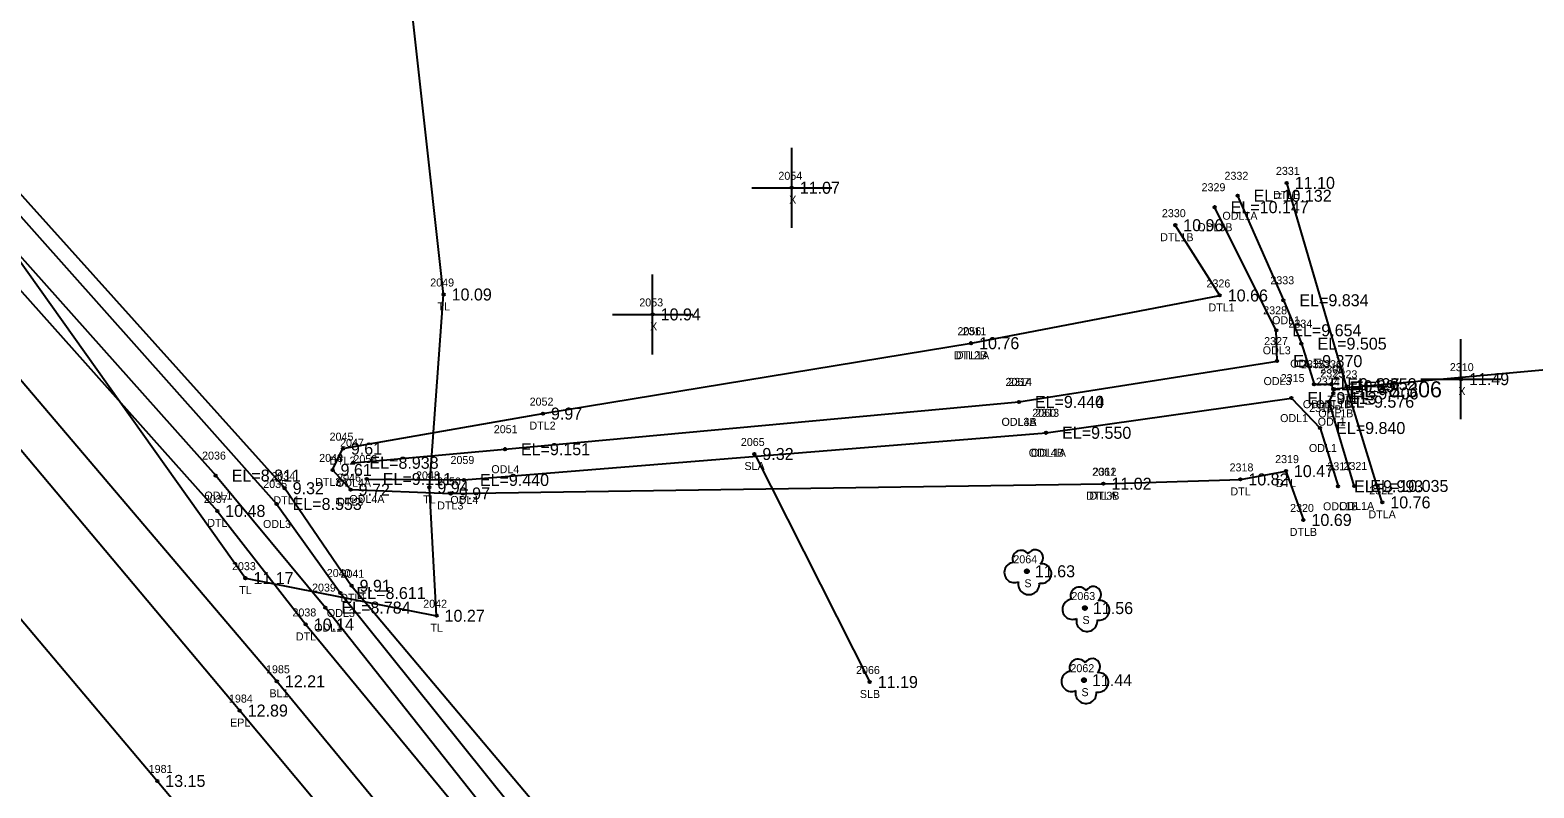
# Model space of a CAD drawing. Extents: x 2042211 to 2045853, y 303080 to 309569.
# Drawn here: x 2044179.7 to 2044367.6, y 305031.1 to 305125.9 of the extents above; entities that cross this region are included whole.
import ezdxf

# ---------------------------------------------------------------- set-up
doc = ezdxf.new("R2010")
doc.units = 0
for name, color, linetype in [('BR_500YR_SCOUR', 7, 'Continuous'), ('RD_DTM_BkLn1', 7, 'Continuous'), ('RD_DTM_BkLn_txCode', 7, 'Continuous'), ('RD_EX_DR_Pipe_txCode', 7, 'Continuous'), ('RD_EX_H2O', 7, 'Continuous'), ('RD_EX_H2O_txCode', 7, 'Continuous'), ('RD_EX_Misc', 7, 'Continuous'), ('RD_EX_Misc_txCode', 7, 'Continuous'), ('RD_EX_Road', 7, 'Continuous'), ('RD_EX_Road_txCode', 7, 'Continuous'), ('RD_EX_TX_H2O_ELEV', 7, 'Continuous'), ('RD_EX_TX_Misc_ELEV', 7, 'Continuous'), ('RD_EX_TX_Road_ELEV', 7, 'Continuous'), ('RD_EX_TX_VEG_ELEV', 7, 'Continuous'), ('RD_EX_VEG_txCode', 7, 'Continuous'), ('RD_HC_Survey_ELEV', 7, 'Continuous'), ('RD_HC_Survey_txCode', 7, 'Continuous'), ('RD_SMD_Locator', 7, 'Continuous'), ('RD_TX_Pipe_ElevEX', 7, 'Continuous')]:
    doc.layers.add(name, color=color, linetype=linetype)

msp = doc.modelspace()

# ---------------------------------------------------------------- linework, layer by layer
at = {"layer": 'BR_500YR_SCOUR'}
for p, q in [((2044376.14, 305084.11), (2044342.61, 305081.01)), ((2044270.23, 305072.92), (2044284.64, 305044.4))]:
    msp.add_line(p, q, dxfattribs=at)
msp.add_lwpolyline([(2044203.29, 305185.8), (2044187.09, 305153.29), (2044169.64, 305138.38), (2044164.21, 305129.35), (2044163.7, 305117.76), (2044206.63, 305057.39), (2044230.52, 305052.69), (2044229.62, 305068.74), (2044231.4, 305092.87), (2044226.11, 305140.65)], dxfattribs=at)
for centre, radius in [((2044231.4, 305092.87), 0.15), ((2044342.61, 305081.01), 0.2), ((2044270.23, 305072.92), 0.15), ((2044229.62, 305068.74), 0.15), ((2044304.28, 305058.25), 0.25), ((2044304.28, 305058.25), 0.15), ((2044206.63, 305057.39), 0.15), ((2044230.52, 305052.69), 0.15), ((2044311.53, 305053.65), 0.25), ((2044311.53, 305053.65), 0.15), ((2044284.64, 305044.4), 0.15), ((2044311.41, 305044.63), 0.25), ((2044311.41, 305044.63), 0.15)]:
    msp.add_circle(centre, radius, dxfattribs=at)
for centre, radius, start, end in [((2044303.56, 305059.79), 1.08, 34.9763, 204.756), ((2044305.32, 305059.95), 0.995, 308.7626, 152.0467), ((2044302.72, 305058.09), 1.26, 96.4518, 294.734), ((2044306.12, 305057.97), 1.22, 256.5667, 98.1046), ((2044304.52, 305056.65), 1.32, 166.8827, 5.7589), ((2044310.81, 305055.19), 1.08, 34.9763, 204.756), ((2044312.58, 305055.35), 0.995, 308.7626, 152.0467), ((2044309.97, 305053.49), 1.26, 96.4518, 294.734), ((2044313.37, 305053.37), 1.22, 256.5667, 98.1046), ((2044311.78, 305052.05), 1.32, 166.8827, 5.7589), ((2044310.69, 305046.18), 1.08, 34.9763, 204.756), ((2044312.46, 305046.33), 0.995, 308.7626, 152.0467), ((2044309.85, 305044.48), 1.26, 96.4518, 294.734), ((2044313.25, 305044.35), 1.22, 256.5667, 98.1046), ((2044311.66, 305043.04), 1.32, 166.8827, 5.7589)]:
    msp.add_arc(centre, radius, start, end, dxfattribs=at)
at = {"layer": 'RD_DTM_BkLn1'}
for points in [[(2043537.57, 305841.2), (2043543.07, 305834.82), (2043547.67, 305836.32), (2043557.54, 305825.5), (2043571.92, 305809.49), (2043633.83, 305732.88), (2043699.09, 305656.29), (2043762.93, 305580.55), (2043827.21, 305502.36), (2043888.69, 305425.33), (2043954.53, 305349.45), (2044014.08, 305277.47), (2044018.49, 305276.45), (2044019.61, 305275.44), (2044023.1, 305269.64), (2044024.11, 305264.85), (2044081.02, 305196.95), (2044145.48, 305121.13), (2044210.56, 305044.49), (2044273.6, 304967.95), (2044321.18, 304912.75), (2044337.82, 304895.78)], [(2043528.91, 305830.2), (2043556.35, 305797.19), (2043619.96, 305720.85), (2043684.02, 305644.21), (2043747.98, 305567.9), (2043812.35, 305491.13), (2043876, 305414.64), (2043940.22, 305337.83), (2044003.86, 305261.82), (2044067.88, 305184.94), (2044131, 305108.73), (2044195.62, 305032.03), (2044259.59, 304955.88), (2044323.63, 304879.52), (2044387.48, 304802.4), (2044451.92, 304725.21), (2044515.94, 304648.42), (2044581.15, 304571.52), (2044645.01, 304495.17), (2044708.42, 304418.52), (2044772.84, 304341.13)]]:
    msp.add_lwpolyline(points, dxfattribs=at)
at = {"layer": 'RD_EX_H2O'}
for points in [[(2044033.22, 305275.98), (2044035.9, 305278.5), (2044040.04, 305277.28), (2044042.29, 305273.95), (2044048.6, 305260.29), (2044090.99, 305205.39), (2044151.22, 305127.18), (2044154.78, 305124.28), (2044202.92, 305070.22), (2044216.63, 305053.71), (2044279.58, 304974.12), (2044337.99, 304907.57), (2044344.68, 304901.99)], [(2044036.31, 305275.77), (2044038.93, 305275.76), (2044040.37, 305274.17), (2044045.78, 305258.87), (2044089.4, 305204.02), (2044149.36, 305125.44), (2044152.21, 305122.89), (2044203.11, 305065.8), (2044214.18, 305051.6), (2044278.81, 304973.18), (2044336.46, 304906.31), (2044343.82, 304899.94), (2044347.6, 304901.86)], [(2044052.64, 305262.28), (2044093.07, 305207.37), (2044155.92, 305130.37), (2044157.38, 305130.75), (2044170.33, 305147.63), (2044181.38, 305159.73), (2044197.15, 305188.95), (2044208.08, 305219.28), (2044210.72, 305219.24), (2044215.12, 305217.08), (2044202.83, 305184.83), (2044185.43, 305151.79), (2044169.6, 305138.4), (2044160.58, 305125.38), (2044211.54, 305068.64), (2044219.9, 305056.44), (2044285.19, 304978.84), (2044339.94, 304911.4), (2044347.53, 304904.82), (2044347.6, 304901.86)], [(2044211.75, 305214.4), (2044200.54, 305185.5), (2044183.75, 305152.21), (2044168.79, 305139.58), (2044158.66, 305124.96), (2044210.53, 305066.67), (2044218.51, 305055.53), (2044282.21, 304976.06), (2044339.42, 304909.19), (2044345.98, 304903.69)], [(2044330.6, 305105.22), (2044336.33, 305092.15), (2044338.59, 305086.72), (2044340.17, 305081.65), (2044342.32, 305081.65)], [(2044348.69, 305066.87), (2044344.23, 305081.39), (2044336.75, 305106.83)], [(2044303.28, 305079.44), (2044335.55, 305084.54), (2044335.44, 305088.39), (2044327.74, 305103.79)], [(2044297.31, 305086.78), (2044328.38, 305092.75), (2044322.82, 305101.54)], [(2044217.52, 305070.93), (2044218.81, 305073.59), (2044243.81, 305077.97), (2044297.31, 305086.78)], [(2044220.13, 305071.82), (2044239.06, 305073.52), (2044303.28, 305079.44)], [(2044306.68, 305075.57), (2044337.33, 305079.91), (2044340.92, 305076.17), (2044343.16, 305068.88)], [(2044345.19, 305068.92), (2044342.03, 305079.46), (2044342.57, 305080.5)], [(2044221.8, 305069.79), (2044233.93, 305069.67), (2044306.68, 305075.57)], [(2044217.52, 305070.93), (2044219.78, 305068.46), (2044232.29, 305067.98), (2044313.84, 305069.2)], [(2044313.84, 305069.2), (2044330.95, 305069.74), (2044336.64, 305070.78), (2044338.84, 305064.67)]]:
    msp.add_lwpolyline(points, dxfattribs=at)
at = {"layer": 'RD_EX_Misc'}
for p, q in [((2044274.9, 305101.22), (2044274.9, 305111.22)), ((2044269.9, 305106.22), (2044279.9, 305106.22)), ((2044257.52, 305085.38), (2044257.52, 305095.38)), ((2044252.52, 305090.38), (2044262.52, 305090.38)), ((2044358.52, 305077.28), (2044358.52, 305087.28)), ((2044353.52, 305082.28), (2044363.52, 305082.28))]:
    msp.add_line(p, q, dxfattribs=at)
at = {"layer": 'RD_EX_Road'}
msp.add_lwpolyline([(2044013.41, 305270.34), (2044077.97, 305194.15), (2044141.4, 305117.67), (2044205.92, 305040.83), (2044269.54, 304964.65), (2044331.73, 304891.04), (2044335.22, 304889.2), (2044346.01, 304875.31), (2044356.18, 304867.61), (2044370.01, 304868.14), (2044386.83, 304866.36), (2044389.44, 304849.53), (2044390.71, 304830.73), (2044393.77, 304818.44), (2044395.5, 304814.18), (2044398.16, 304811.09), (2044461.8, 304734.03), (2044526.04, 304657.6), (2044591.28, 304580.23), (2044655.29, 304503.62), (2044718.26, 304427.32), (2044783.13, 304349.86)], dxfattribs=at)
at = {"layer": 'RD_SMD_Locator'}
for centre in [(2044274.9, 305106.22), (2044330.6, 305105.22), (2044336.75, 305106.83), (2044327.74, 305103.79), (2044322.82, 305101.54), (2044328.38, 305092.75), (2044336.33, 305092.15), (2044257.52, 305090.38), (2044335.44, 305088.39), (2044297.31, 305086.78), (2044297.31, 305086.78), (2044338.59, 305086.72), (2044335.55, 305084.54), (2044340.17, 305081.65), (2044342.32, 305081.65), (2044344.23, 305081.39), (2044358.52, 305082.28), (2044303.28, 305079.44), (2044303.28, 305079.44), (2044337.33, 305079.91), (2044342.03, 305079.46), (2044342.57, 305080.5), (2044243.81, 305077.97), (2044306.68, 305075.57), (2044306.68, 305075.57), (2044340.92, 305076.17), (2044218.81, 305073.59), (2044239.06, 305073.52), (2044220.13, 305071.82), (2044202.92, 305070.22), (2044217.52, 305070.93), (2044217.52, 305070.93), (2044221.8, 305069.79), (2044233.93, 305069.67), (2044330.95, 305069.74), (2044336.64, 305070.78), (2044211.54, 305068.64), (2044219.78, 305068.46), (2044232.29, 305067.98), (2044313.84, 305069.2), (2044313.84, 305069.2), (2044343.16, 305068.88), (2044345.19, 305068.92), (2044203.11, 305065.8), (2044210.53, 305066.67), (2044348.69, 305066.87), (2044338.84, 305064.67), (2044219.9, 305056.44), (2044218.51, 305055.53), (2044216.63, 305053.71), (2044214.18, 305051.6), (2044210.56, 305044.49), (2044205.92, 305040.83), (2044195.62, 305032.03)]:
    msp.add_circle(centre, 0.15, dxfattribs=at)

# ---------------------------------------------------------------- texts
at = {"layer": 'RD_DTM_BkLn_txCode'}
for s, p in [('1985', (2044209.21, 305045.49)), ('BL1', (2044209.64, 305042.49))]:
    msp.add_text(s, height=1, dxfattribs=at).set_placement(p)
at = {"layer": 'RD_EX_DR_Pipe_txCode'}
for s, p in [('2309', (2044340.94, 305083.01)), ('PB', (2044341.83, 305078.01))]:
    msp.add_text(s, height=1, dxfattribs=at).set_placement(p)
at = {"layer": 'RD_EX_H2O_txCode'}
for s, p in [('2332', (2044328.97, 305107.22)), ('2331', (2044335.4, 305107.83)), ('2329', (2044326.11, 305105.79)), ('DTLB', (2044335.03, 305104.83)), ('2330', (2044321.15, 305102.54)), ('ODL3B', (2044325.58, 305100.79)), ('ODL1A', (2044328.71, 305102.22)), ('DTL1B', (2044320.94, 305099.54)), ('2326', (2044326.72, 305093.75)), ('2333', (2044334.7, 305094.15)), ('DTL1', (2044326.97, 305090.75)), ('2328', (2044333.81, 305090.39)), ('ODL1', (2044334.92, 305089.15)), ('2056', (2044295.61, 305087.78)), ('2311', (2044296.24, 305087.78)), ('2334', (2044336.96, 305088.72)), ('ODL3', (2044333.75, 305085.39)), ('2327', (2044333.92, 305086.54)), ('DTL2B', (2044295.14, 305084.78)), ('DTL1A', (2044295.41, 305084.78)), ('ODL1', (2044337.18, 305083.72)), ('2335', (2044338.54, 305083.65)), ('2336', (2044340.67, 305083.65)), ('2315', (2044335.99, 305081.91)), ('2325', (2044340.94, 305082.5)), ('2323', (2044342.6, 305082.39)), ('2057', (2044301.61, 305081.44)), ('2314', (2044301.94, 305081.44)), ('ODL3', (2044333.85, 305081.54)), ('2324', (2044340.4, 305081.46)), ('2052', (2044242.15, 305078.97)), ('ODL1', (2044338.76, 305078.65)), ('2316', (2044339.55, 305078.17)), ('ODL1B', (2044340.44, 305078.65)), ('DTL', (2044342.99, 305079.39)), ('DTL2', (2044242.12, 305075.97)), ('ODL3A', (2044301.1, 305076.44)), ('ODL4B', (2044301.12, 305076.44)), ('2060', (2044304.95, 305077.57)), ('2313', (2044305.33, 305077.57)), ('ODL1', (2044335.92, 305076.91)), ('ODL1', (2044340.62, 305076.46)), ('ODL1B', (2044340.69, 305077.5)), ('2045', (2044217.15, 305074.59)), ('2051', (2044237.67, 305075.52)), ('2036', (2044201.22, 305072.22)), ('2047', (2044218.46, 305073.82)), ('ODL4B', (2044304.51, 305072.57)), ('ODL1A', (2044304.78, 305072.57)), ('ODL1', (2044339.52, 305073.17)), ('2043', (2044215.85, 305071.93)), ('2044', (2044215.85, 305071.93)), ('DTL2', (2044217.12, 305071.59)), ('2058', (2044220.13, 305071.79)), ('2059', (2044232.26, 305071.67)), ('ODL4', (2044237.36, 305070.52)), ('2318', (2044329.61, 305070.74)), ('2319', (2044335.3, 305071.78)), ('2317', (2044341.82, 305070.88)), ('2321', (2044343.84, 305070.92)), ('2035', (2044208.86, 305068.67)), ('2034', (2044209.87, 305069.64)), ('DTL2A', (2044215.34, 305068.93)), ('DTL3A', (2044215.34, 305068.93)), ('ODL4A', (2044217.95, 305068.82)), ('2046', (2044218.09, 305069.46)), ('2050', (2044230.58, 305068.98)), ('2061', (2044312.43, 305070.2)), ('2312', (2044312.5, 305070.2)), ('DTL', (2044335.4, 305068.78)), ('2037', (2044201.44, 305066.8)), ('ODL1', (2044201.51, 305067.22)), ('DTL1', (2044210.13, 305066.64)), ('ODL4A', (2044219.62, 305066.79)), ('ODL4', (2044232.24, 305066.67)), ('DTL3B', (2044311.68, 305067.2)), ('DTLA', (2044312.11, 305067.2)), ('DTL', (2044329.71, 305067.74)), ('2322', (2044347.06, 305067.87)), ('DTL3', (2044218.09, 305066.46)), ('DTL3', (2044230.6, 305065.98)), ('2320', (2044337.17, 305065.67)), ('ODL1B', (2044341.28, 305065.88)), ('ODL1A', (2044343.29, 305065.92)), ('DTLA', (2044346.96, 305064.87)), ('DTL', (2044201.87, 305063.8)), ('ODL3', (2044208.83, 305063.67)), ('DTLB', (2044337.12, 305062.67)), ('2040', (2044216.8, 305057.53)), ('2041', (2044218.51, 305057.44)), ('2039', (2044214.96, 305055.71)), ('DTL1', (2044218.49, 305054.44)), ('2038', (2044212.51, 305052.6)), ('ODL3', (2044216.81, 305052.53)), ('ODL1', (2044215.22, 305050.71)), ('DTL', (2044212.94, 305049.6))]:
    msp.add_text(s, height=1, dxfattribs=at).set_placement(p)
at = {"layer": 'RD_EX_Misc_txCode'}
for s, p in [('2054', (2044273.23, 305107.22)), ('X', (2044274.58, 305104.22)), ('2053', (2044255.85, 305091.38)), ('X', (2044257.2, 305088.38)), ('2310', (2044357.13, 305083.28)), ('X', (2044358.2, 305080.28))]:
    msp.add_text(s, height=1, dxfattribs=at).set_placement(p)
at = {"layer": 'RD_EX_Road_txCode'}
for s, p in [('1984', (2044204.58, 305041.83)), ('EPL', (2044204.72, 305038.83))]:
    msp.add_text(s, height=1, dxfattribs=at).set_placement(p)
at = {"layer": 'RD_EX_TX_H2O_ELEV'}
for s, p in [('11.10', (2044337.75, 305106.08)), ('EL=10.132', (2044332.6, 305104.47)), ('EL=10.147', (2044329.74, 305103.04)), ('10.96', (2044323.82, 305100.79)), ('10.66', (2044329.38, 305092)), ('EL=9.834', (2044338.33, 305091.4)), ('EL=9.654', (2044337.44, 305087.64)), ('10.76', (2044298.31, 305086.03)), ('10.76', (2044298.31, 305086.03)), ('EL=9.505', (2044340.59, 305085.97)), ('EL=9.370', (2044337.55, 305083.79)), ('EL=9.427', (2044342.17, 305080.9)), ('EL=9.652', (2044344.32, 305080.9)), ('EL=9.406', (2044344.57, 305079.75)), ('10.39', (2044345.23, 305080.64)), ('EL=9.444', (2044305.28, 305078.69)), ('EL=9.440', (2044305.28, 305078.69)), ('EL=9.113', (2044339.33, 305079.16)), ('EL=9.576', (2044344.03, 305078.71)), ('9.97', (2044244.81, 305077.22)), ('EL=9.840', (2044342.92, 305075.42)), ('EL=9.550', (2044308.68, 305074.82)), ('EL=9.550', (2044308.68, 305074.82)), ('9.61', (2044219.81, 305072.84)), ('EL=9.151', (2044241.06, 305072.77)), ('9.61', (2044218.52, 305070.18)), ('9.61', (2044218.52, 305070.18)), ('EL=8.938', (2044222.13, 305071.07)), ('10.47', (2044337.64, 305070.03)), ('EL=8.811', (2044204.92, 305069.47)), ('EL=9.111', (2044223.8, 305069.04)), ('EL=9.440', (2044235.93, 305068.92)), ('11.02', (2044314.84, 305068.45)), ('11.02', (2044314.84, 305068.45)), ('10.82', (2044331.95, 305068.99)), ('EL=9.993', (2044345.16, 305068.13)), ('EL=10.035', (2044347.19, 305068.17)), ('9.32', (2044212.54, 305067.89)), ('9.72', (2044220.78, 305067.71)), ('9.97', (2044233.29, 305067.23)), ('10.76', (2044349.69, 305066.12)), ('10.48', (2044204.11, 305065.05)), ('EL=8.553', (2044212.53, 305065.92)), ('10.69', (2044339.84, 305063.92)), ('EL=8.611', (2044220.51, 305054.78)), ('9.91', (2044220.9, 305055.69)), ('EL=8.784', (2044218.63, 305052.96)), ('10.14', (2044215.18, 305050.85))]:
    msp.add_text(s, height=1.5, dxfattribs=at).set_placement(p)
at = {"layer": 'RD_EX_TX_Misc_ELEV'}
for s, p in [('11.07', (2044275.9, 305105.47)), ('10.94', (2044258.52, 305089.63)), ('11.49', (2044359.52, 305081.53)), ('12.21', (2044211.56, 305043.74))]:
    msp.add_text(s, height=1.5, dxfattribs=at).set_placement(p)
at = {"layer": 'RD_EX_TX_Road_ELEV'}
msp.add_text('12.89', height=1.5, dxfattribs=at).set_placement((2044206.92, 305040.08))
at = {"layer": 'RD_EX_TX_VEG_ELEV'}
for s, p in [('10.09', (2044232.4, 305092.12)), ('9.32', (2044271.23, 305072.17)), ('9.94', (2044230.62, 305067.99)), ('11.63', (2044305.28, 305057.5)), ('11.17', (2044207.63, 305056.64)), ('11.56', (2044312.53, 305052.9)), ('10.27', (2044231.52, 305051.94)), ('11.19', (2044285.64, 305043.65)), ('11.44', (2044312.41, 305043.88))]:
    msp.add_text(s, height=1.5, dxfattribs=at).set_placement(p)
at = {"layer": 'RD_EX_VEG_txCode'}
for s, p in [('2049', (2044229.73, 305093.87)), ('TL', (2044230.63, 305090.87)), ('2065', (2044268.54, 305073.92)), ('SLA', (2044268.99, 305070.92)), ('2048', (2044227.95, 305069.74)), ('TL', (2044228.85, 305066.74)), ('2064', (2044302.59, 305059.25)), ('2033', (2044204.96, 305058.39)), ('TL', (2044205.86, 305055.39)), ('S', (2044303.97, 305056.25)), ('2042', (2044228.85, 305053.69)), ('2063', (2044309.84, 305054.65)), ('S', (2044311.23, 305051.65)), ('TL', (2044229.75, 305050.69)), ('2066', (2044282.93, 305045.4)), ('2062', (2044309.72, 305045.63)), ('SLB', (2044283.41, 305042.4)), ('S', (2044311.1, 305042.63))]:
    msp.add_text(s, height=1, dxfattribs=at).set_placement(p)
at = {"layer": 'RD_HC_Survey_ELEV'}
msp.add_text('13.15', height=1.5, dxfattribs=at).set_placement((2044196.62, 305031.28))
at = {"layer": 'RD_HC_Survey_txCode'}
msp.add_text('1981', height=1, dxfattribs=at).set_placement((2044194.55, 305033.03))
at = {"layer": 'RD_TX_Pipe_ElevEX'}
msp.add_text('EL=8.306', height=2, dxfattribs=at).set_placement((2044344.61, 305080.01))

doc.saveas('drawing.dxf')
